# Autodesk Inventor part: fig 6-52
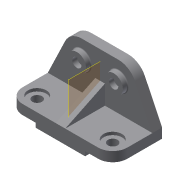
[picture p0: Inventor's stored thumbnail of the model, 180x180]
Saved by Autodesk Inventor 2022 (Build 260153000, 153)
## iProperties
Created: 2001-12
Part Number: fig 6-52
Document SubType Name: Modeling
Designer: Renu Muthoo
Density: 1 g/cm^3
Material: Generic
Appearance: Default
Control State: 0
Master: False
Checked Out: False
Shininess: 77.0
Length Units: 11269
Angle Units: 11279
Time Units: 11290
Mass Units: 11283
Length Display Precision: 3
Angle Display Precision: 2
Density: 0.0
Volumn: 0.0
Area: 0.0
PropertySet Name: Model Information
Author: Renu Muthoo
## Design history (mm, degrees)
node "Sketch1"
sketch "Sketch2"
  geometry: L1 (-67.219, 19.116)-(148.781, 19.116); L2 (148.781, 19.116)-(148.781, -0.884); L3 (-67.219, -0.884)-(-67.219, 19.116); L4 (-10.219, -0.884)-(-10.219, -9.884); L5 (-10.219, -9.884)-(91.781, -9.884); L6 (91.781, -9.884)-(91.781, -0.884); L7 (148.781, -0.884)-(91.781, -0.884); L8 (-10.219, -0.884)-(-67.219, -0.884)
  constraints: 16 end point, 5 parallel, 4 perpendicular, 2 equal length, 1 horizontal
  dimensions: "d0" = 102 distance of L4.end L5.end; "d1" = 57 distance of L4.start L3.start; "d2" = 29 distance between parallel lines of L1 L5; "d3" = 20 distance of L1.end L2.end
extrude "Extrusion1" new body sketch "Sketch2" distance "d4" = 102; taper "d5" = 0 deg
sketch "Sketch3"
  geometry: L1 (67.219, -19.116)-(-148.781, -19.116) reference; L2 (67.219, -19.116)-(31.475, -93.564); L3 (-2.781, -115.116)-(-78.781, -115.116); L4 (-113.038, -93.564)-(-148.781, -19.116); A1 r 38 centre (-2.781, -77.116) between (-2.781, -115.116) and (31.475, -93.564); A2 r 38 centre (-78.781, -77.116) between (-113.038, -93.564) and (-78.781, -115.116)
  constraints: 6 end point, 4 point on circle, 4 tangent, 2 centre point, 1 equal length, 1 equal radius, 1 parallel
  dimensions: "d6" = 96 distance between parallel lines of L3 L1; "d7" = 38 radius of A1; "d8" = 76 distance of A2.centre A1.centre
extrude "Extrusion2" join sketch "Sketch3" distance "d9" = 20; taper "d10" = 0 deg
fillet "Fillet1" dims "d11" = 30
workplane "Work Plane1"
sketch "Sketch5"
  geometry: A1 r 30 centre (-30, 0) between (-30, -30) and (0, 0) reference; 1 further point
  constraints: 1 coincident
hole "Hole1" sketch "Sketch5" at (-30, 0) diameter "d16" = 20; stored, may be unused: countersink angle "d20" = 82 deg, drill point angle "d22" = 118 deg; dims "d17" = 6, "d18" = 38, "d19" = 6, "d21" = 8
sketch "Sketch6"
  geometry: C1 r 19 at (-2.781, 77.116); C2 r 9.5 at (-2.781, 77.116); A1 r 38 centre (-2.781, 77.116) between (31.475, 93.564) and (-2.781, 115.116) reference
  constraints: 2 centre point, 2 coincident
  dimensions: "d23" = 38 diameter of C1; "d24" = 19 diameter of C2
extrude "Extrusion3" join sketch "Sketch6" distance "d25" = 10; taper "d26" = 0 deg
sketch "Sketch7"
  geometry: L1 (0, -82)-(-39.557, 0); L2 (0, -82)-(20, -82) reference; L3 (29, 22.405)-(29, -82); L4 (29, -82)-(0, -82); L5 (0, -82)-(0, 0); L6 (0, 0)-(-90.034, 0); L7 (-90.034, 0)-(-90.034, 22.405); L8 (-90.034, 22.405)-(29, 22.405); L9 (0, 0)-(-74.447, 0) reference
  constraints: 14 end point, 1 collinear, 1 point on line
feature "Rib3" sketch "Sketch7" dims "d35" = 10, "d36" = 20
fillet "Fillet3" dims "d37" = 2
mirror "Mirror4"
body "Solid1"
other parameters: "d12" = -108
